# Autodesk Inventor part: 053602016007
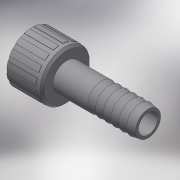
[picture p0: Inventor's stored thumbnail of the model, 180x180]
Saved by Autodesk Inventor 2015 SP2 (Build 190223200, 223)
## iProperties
Created: 2017-10
Part Number: 053602016007
Material: Generic
Description: PLASSON HOSE NOZZLE+NUT/THR. 3/4"-16
Document SubType Name: Modeling
Designer: KIM
Density: 1 g/cm^3
Appearance: Default
Author: KIM
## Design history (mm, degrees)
derived "053602.ipt"
feature "Solid1::053602.ipt"
tag "TaggingFeature1"
body "Solid1"
other parameters: "d0" = 67, "d1" = 170 deg, "d2" = 16, "d5" = 28.9404, "d6" = 11.2, "d8" = 26.8, "d9" = 24.117, "d10" = 20.1, "d11" = 12.06, "d12" = 16.75, "d13" = 28.45806, "d14" = 1.20585, "d17" = 2.4117, "d18" = 1.20585, "d19" = 18.76, "d20" = 0, "d22" = 360 deg, "d_" = 16, "E_" = 16, "H_" = 67, "G_" = 24.117
